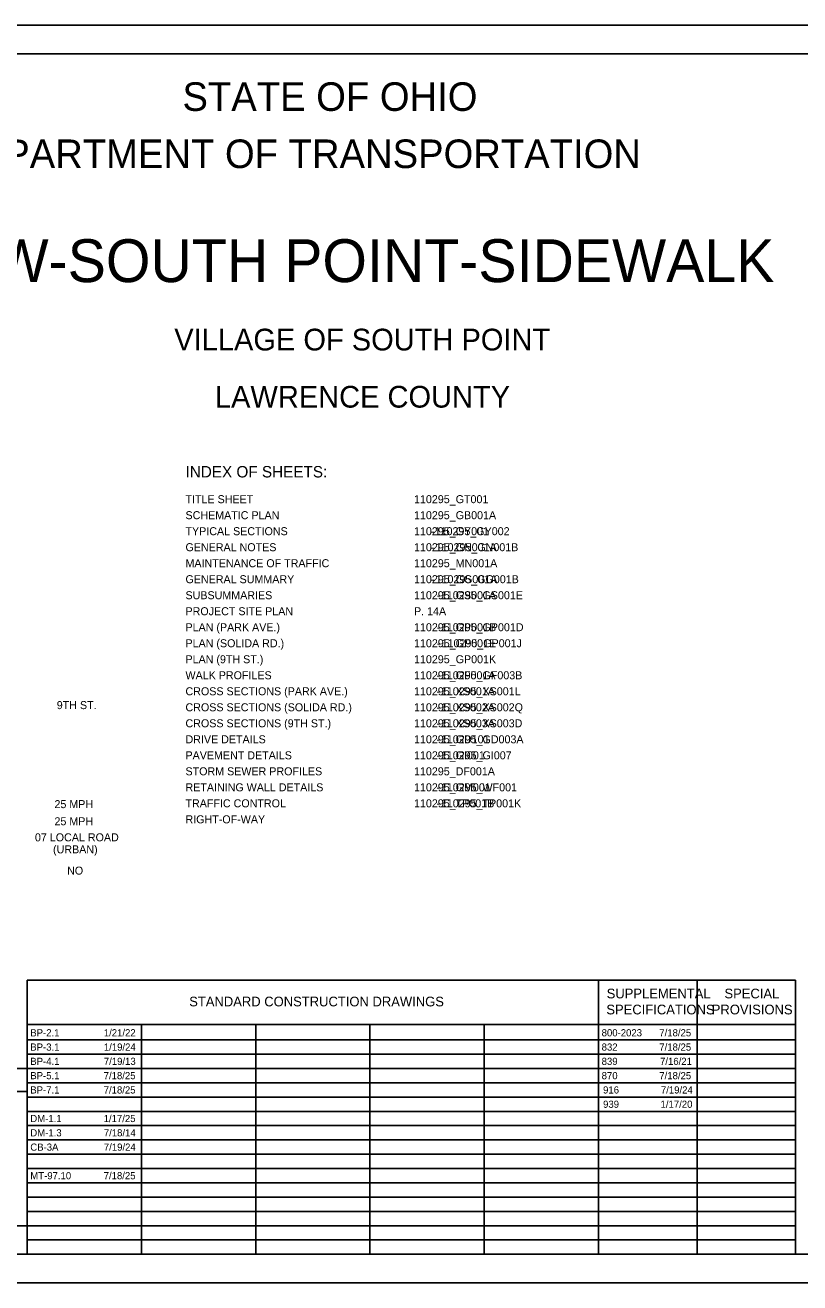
# Model space of a CAD drawing. Extents: x 0 to 45.4, y -2.2 to 22.
# Drawn here: x 11.21 to 24.77, y 0 to 22 of the extents above; entities that cross this region are included whole.
import ezdxf

# ---------------------------------------------------------------- set-up
doc = ezdxf.new("R2010")
doc.units = 0
for name, color, linetype in [('SH_Border', 7, 'Continuous'), ('SH_Cut_Line', 7, 'Continuous'), ('SH_Data', 7, 'Continuous'), ('SH_Text', 7, 'Continuous')]:
    doc.layers.add(name, color=color, linetype=linetype)

msp = doc.modelspace()

# ---------------------------------------------------------------- linework, layer by layer
at = {"layer": 'SH_Border'}
msp.add_lwpolyline([(1.5, 21.5), (33.5, 21.5), (33.5, 0.5), (1.5, 0.5)], close=True, dxfattribs=at)
at = {"layer": 'SH_Cut_Line'}
msp.add_lwpolyline([(0, 0), (34, 0), (34, 22), (0, 22)], close=True, dxfattribs=at)
at = {"layer": 'SH_Data'}
for p, q in [((11.25, 5.292), (24.7, 5.292)), ((11.25, 0.5), (11.25, 5.292)), ((21.25, 0.5), (21.25, 5.292)), ((22.975, 0.5), (22.975, 5.292)), ((24.7, 0.5), (24.7, 5.292)), ((11.25, 4.521), (24.7, 4.521)), ((13.25, 0.5), (13.25, 4.521)), ((15.25, 0.5), (15.25, 4.521)), ((17.25, 0.5), (17.25, 4.521)), ((19.25, 0.5), (19.25, 4.521)), ((11.25, 4.25), (24.7, 4.25)), ((11.25, 4), (24.7, 4)), ((11.25, 3.75), (8.45, 3.75)), ((11.25, 3.75), (24.7, 3.75)), ((11.25, 0.5), (11.25, 3.75)), ((11.25, 3.35), (8.45, 3.35)), ((11.25, 3.5), (24.7, 3.5)), ((11.25, 3.25), (24.7, 3.25)), ((11.25, 3), (24.7, 3)), ((11.25, 2.75), (24.7, 2.75)), ((11.25, 2.5), (24.7, 2.5)), ((11.25, 2.25), (24.7, 2.25)), ((11.25, 2), (24.7, 2)), ((11.25, 1.75), (24.7, 1.75)), ((11.25, 1.5), (24.7, 1.5)), ((11.25, 1.25), (24.7, 1.25)), ((11.25, 1), (24.7, 1)), ((11.25, 0.75), (24.7, 0.75)), ((11.25, 0.5), (8.45, 0.5))]:
    msp.add_line(p, q, dxfattribs=at)
msp.add_lwpolyline([(11.25, 0.5), (11.25, 1), (8.45, 1), (8.45, 0.5)], close=True, dxfattribs=at)

# ---------------------------------------------------------------- texts
at = {"layer": 'SH_Text'}
for s, height, p in [('STATE OF OHIO', 0.5, (13.968, 20.5)), ('DEPARTMENT OF TRANSPORTATION', 0.5, (9.92, 19.5)), ('LAW-SOUTH POINT-SIDEWALK', 0.75, (9.452, 17.505)), ('VILLAGE OF SOUTH POINT', 0.38, (13.825, 16.31)), ('LAWRENCE COUNTY', 0.38, (14.536, 15.31)), ('INDEX OF SHEETS:', 0.2, (14.021, 14.088)), ('TITLE SHEET', 0.14, (14.021, 13.638)), ('110295_GT001', 0.14, (18.021, 13.638)), ('SCHEMATIC PLAN', 0.14, (14.021, 13.358)), ('110295_GB001A', 0.14, (18.021, 13.358)), ('TYPICAL SECTIONS', 0.14, (14.021, 13.078)), ('110295_GY001', 0.14, (18.021, 13.078)), ('110295_GY002', 0.14, (18.382, 13.078)), ('-', 0.14, (18.315, 13.078)), ('GENERAL NOTES', 0.14, (14.021, 12.798)), ('110295_GN001A', 0.14, (18.021, 12.798)), ('-', 0.14, (18.312, 12.798)), ('110295_GN001B', 0.14, (18.4, 12.798)), ('MAINTENANCE OF TRAFFIC', 0.14, (14.021, 12.518)), ('110295_MN001A', 0.14, (18.021, 12.518)), ('GENERAL SUMMARY', 0.14, (14.021, 12.238)), ('110295_GG001A', 0.14, (18.021, 12.238)), ('110295_GG001B', 0.14, (18.398, 12.238)), ('-', 0.14, (18.314, 12.238)), ('SUBSUMMARIES', 0.14, (14.021, 11.958)), ('110295_GS001A', 0.14, (18.021, 11.958)), ('-', 0.14, (18.421, 11.958)), ('110295_GS001E', 0.14, (18.491, 11.958)), ('PROJECT SITE PLAN', 0.14, (14.021, 11.678)), ('P. 14A', 0.14, (18.021, 11.678)), ('PLAN (PARK AVE.)', 0.14, (14.021, 11.398)), ('110295_GP001B', 0.14, (18.021, 11.398)), ('-', 0.14, (18.418, 11.398)), ('110295_GP001D', 0.14, (18.491, 11.398)), ('PLAN (SOLIDA RD.)', 0.14, (14.021, 11.118)), ('110295_GP001E', 0.14, (18.021, 11.118)), ('110295_GP001J', 0.14, (18.504, 11.118)), ('-', 0.14, (18.421, 11.118)), ('PLAN (9TH ST.)', 0.14, (14.021, 10.838)), ('110295_GP001K', 0.14, (18.021, 10.838)), ('WALK PROFILES', 0.14, (14.021, 10.558)), ('110295_GF001A', 0.14, (18.021, 10.558)), ('-', 0.14, (18.416, 10.558)), ('110295_GF003B', 0.14, (18.491, 10.558)), ('CROSS SECTIONS (PARK AVE.)', 0.14, (14.021, 10.278)), ('110295_XS001A', 0.14, (18.021, 10.278)), ('110295_XS001L', 0.14, (18.491, 10.278)), ('9TH ST.', 0.14, (11.768, 10.036)), ('CROSS SECTIONS (SOLIDA RD.)', 0.14, (14.021, 9.998)), ('110295_XS002A', 0.14, (18.021, 9.998)), ('-', 0.14, (18.416, 10.278)), ('-', 0.14, (18.416, 10.278)), ('110295_XS002Q', 0.14, (18.491, 9.998)), ('-', 0.14, (18.416, 9.998)), ('-', 0.14, (18.416, 9.998)), ('CROSS SECTIONS (9TH ST.)', 0.14, (14.021, 9.718)), ('110295_XS003A', 0.14, (18.021, 9.718)), ('-', 0.14, (18.416, 9.718)), ('-', 0.14, (18.416, 9.718)), ('110295_XS003D', 0.14, (18.491, 9.718)), ('DRIVE DETAILS', 0.14, (14.021, 9.438)), ('110295_GD101', 0.14, (18.021, 9.438)), ('-', 0.14, (18.416, 9.438)), ('110295_GD003A', 0.14, (18.491, 9.438)), ('PAVEMENT DETAILS', 0.14, (14.021, 9.158)), ('110295_GI001', 0.14, (18.021, 9.158)), ('110295_GI007', 0.14, (18.491, 9.158)), ('-', 0.14, (18.416, 9.158)), ('STORM SEWER PROFILES', 0.14, (14.021, 8.878)), ('110295_DF001A', 0.14, (18.021, 8.878)), ('RETAINING WALL DETAILS', 0.14, (14.021, 8.598)), ('110295_GM001', 0.14, (18.021, 8.598)), ('-', 0.14, (18.416, 8.598)), ('110295_WF001', 0.14, (18.491, 8.598)), ('25 MPH', 0.14, (11.728, 8.304)), ('TRAFFIC CONTROL', 0.14, (14.021, 8.318)), ('110295_TP001B', 0.14, (18.021, 8.318)), ('-', 0.14, (18.416, 8.318)), ('110295_TP001K', 0.14, (18.491, 8.318)), ('25 MPH', 0.14, (11.728, 8.004)), ('RIGHT-OF-WAY', 0.14, (14.021, 8.038)), ('07 LOCAL ROAD', 0.14, (11.386, 7.723)), ('(URBAN)', 0.14, (11.703, 7.513)), ('NO', 0.14, (11.949, 7.141)), ('SUPPLEMENTAL', 0.17, (21.393, 4.976)), ('SPECIAL', 0.17, (23.454, 4.976)), ('STANDARD CONSTRUCTION DRAWINGS', 0.17, (14.086, 4.836)), ('SPECIFICATIONS', 0.17, (21.387, 4.696)), ('PROVISIONS', 0.17, (23.232, 4.696)), ('BP-2.1', 0.125, (11.305, 4.312)), ('1/21/22', 0.125, (12.591, 4.312)), ('800-2023', 0.125, (21.305, 4.312)), ('7/18/25', 0.125, (22.314, 4.312)), ('BP-3.1', 0.125, (11.305, 4.062)), ('1/19/24', 0.125, (12.592, 4.062)), ('832', 0.125, (21.305, 4.062)), ('7/18/25', 0.125, (22.314, 4.062)), ('BP-4.1', 0.125, (11.305, 3.812)), ('7/19/13', 0.125, (12.592, 3.812)), ('839', 0.125, (21.305, 3.812)), ('7/16/21', 0.125, (22.327, 3.812)), ('BP-5.1', 0.125, (11.305, 3.562)), ('7/18/25', 0.125, (12.589, 3.562)), ('870', 0.125, (21.305, 3.562)), ('7/18/25', 0.125, (22.314, 3.562)), ('BP-7.1', 0.125, (11.305, 3.312)), ('7/18/25', 0.125, (12.589, 3.312)), ('916', 0.125, (21.33, 3.312)), ('7/19/24', 0.125, (22.342, 3.312)), ('939', 0.125, (21.33, 3.062)), ('1/17/20', 0.125, (22.336, 3.062)), ('DM-1.1', 0.125, (11.305, 2.812)), ('1/17/25', 0.125, (12.589, 2.812)), ('DM-1.3', 0.125, (11.305, 2.562)), ('7/18/14', 0.125, (12.592, 2.562)), ('CB-3A', 0.125, (11.305, 2.312)), ('7/19/24', 0.125, (12.592, 2.312)), ('MT-97.10', 0.125, (11.305, 1.812)), ('7/18/25', 0.125, (12.589, 1.812))]:
    msp.add_text(s, height=height, dxfattribs=at).set_placement(p)

doc.saveas('drawing.dxf')
